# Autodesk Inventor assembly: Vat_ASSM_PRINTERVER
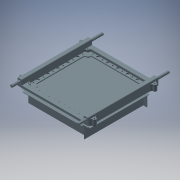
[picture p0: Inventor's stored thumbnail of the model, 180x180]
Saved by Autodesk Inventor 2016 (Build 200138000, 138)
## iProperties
Created: 2015-11
Part Number: Vat_ASSM_PRINTERVER
Document SubType Name: Assembly
Designer: John
Author: John
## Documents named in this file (4)
- D:\3D Printer Designs\John Ledden Designs\DLP Printer\V0-4\Vat_ASSM_PRINTERVER.iam
- D:\3D Printer Designs\John Ledden Designs\DLP Printer\V0-4\Vat_MountingPlate.ipt
- D:\3D Printer Designs\John Ledden Designs\DLP Printer\V0-4\M8_Rod_275mm.ipt
- D:\3D Printer Designs\John Ledden Designs\DLP Printer\V0-4\FlexVat_ASSM.iam
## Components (4 placed, 4 different names)
1. Vat_MountingPlate_1083
2. M8_Rod_275mm_1084
3. M8_Rod_275mm_1085
4. FlexVat_ASSM_1086 [sub-assembly]
